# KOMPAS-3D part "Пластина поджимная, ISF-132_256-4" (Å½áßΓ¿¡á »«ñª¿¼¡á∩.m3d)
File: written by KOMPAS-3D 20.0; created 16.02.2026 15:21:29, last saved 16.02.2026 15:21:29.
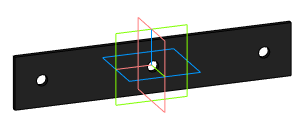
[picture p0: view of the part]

Document properties: Автор: admin; Полное имя файла: P:\INSTART\Технический отдел\ОР\Прочие задачи\КД на номенклатурный ряд\КД на типоразмеры дросселей\Сетевые дроссели ISF\ISF-4\Тип 1\ISF-132_256-4\0723\Новая папка\Пластина поджимная.m3d

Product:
- Part/product: Пластина поджимная  | designation ISF-132_256-4

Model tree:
1. Операция без истории:1

Expressions: ISF-132_256-4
